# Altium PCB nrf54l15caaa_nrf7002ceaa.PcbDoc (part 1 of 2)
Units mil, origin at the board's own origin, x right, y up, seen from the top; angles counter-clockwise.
Board outline 890.45 x 692.95 mil, 6 copper layers (Top Layer, Mid Layer 1, Mid Layer 2, Mid-Layer 3, Mid-Layer 4, Bottom Layer), stack 38.012 mil thick; 75 components, 69 nets, 285 pads, 346 vias.
Unrouted connection lines stored in the file: 4.
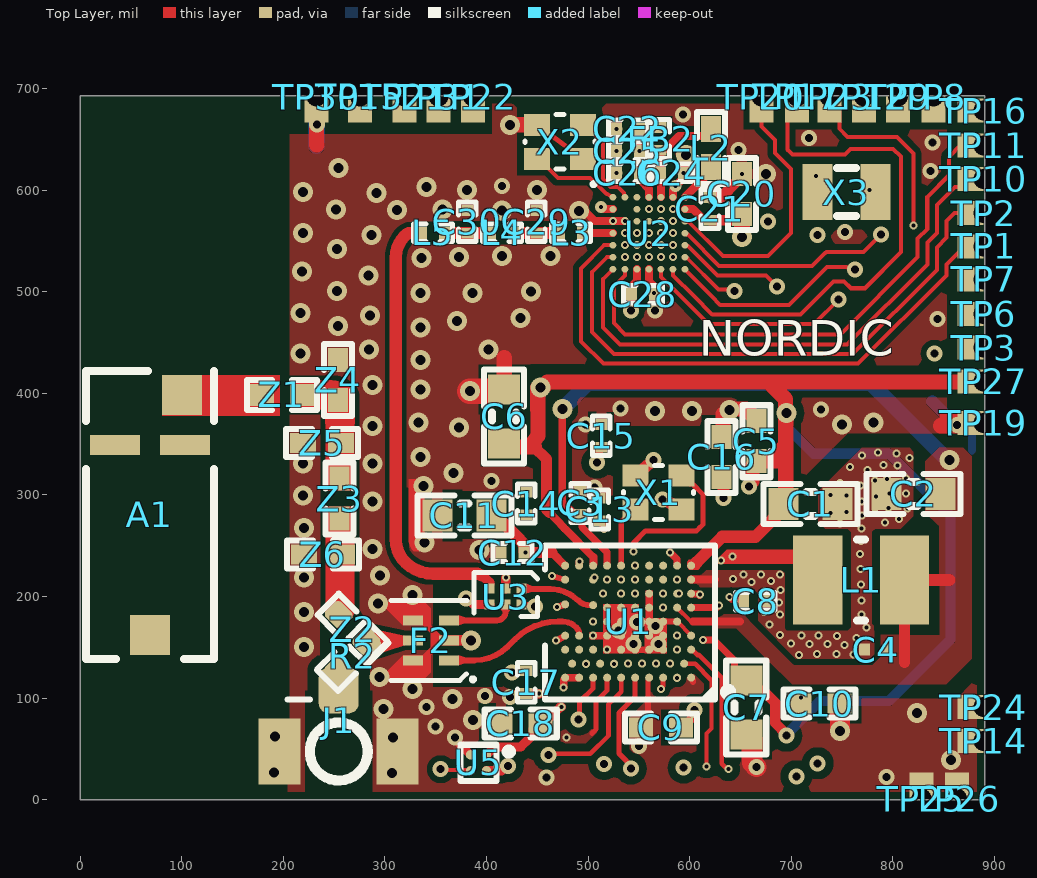
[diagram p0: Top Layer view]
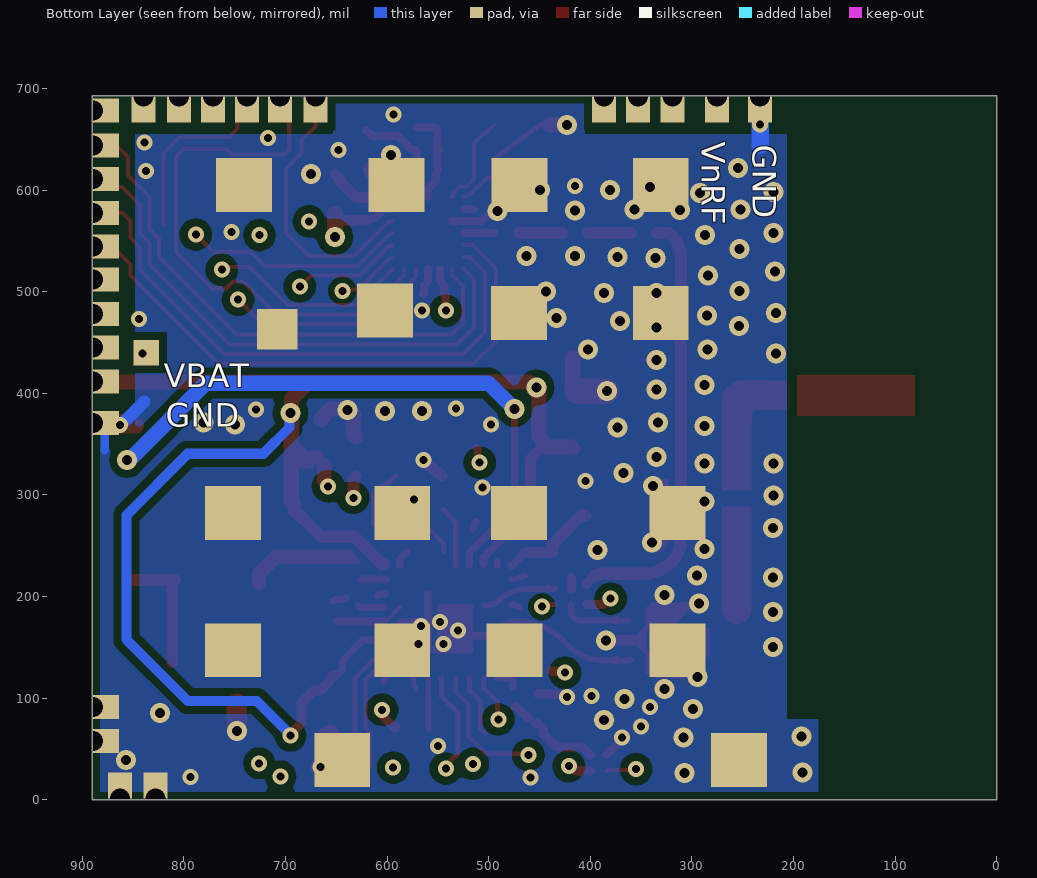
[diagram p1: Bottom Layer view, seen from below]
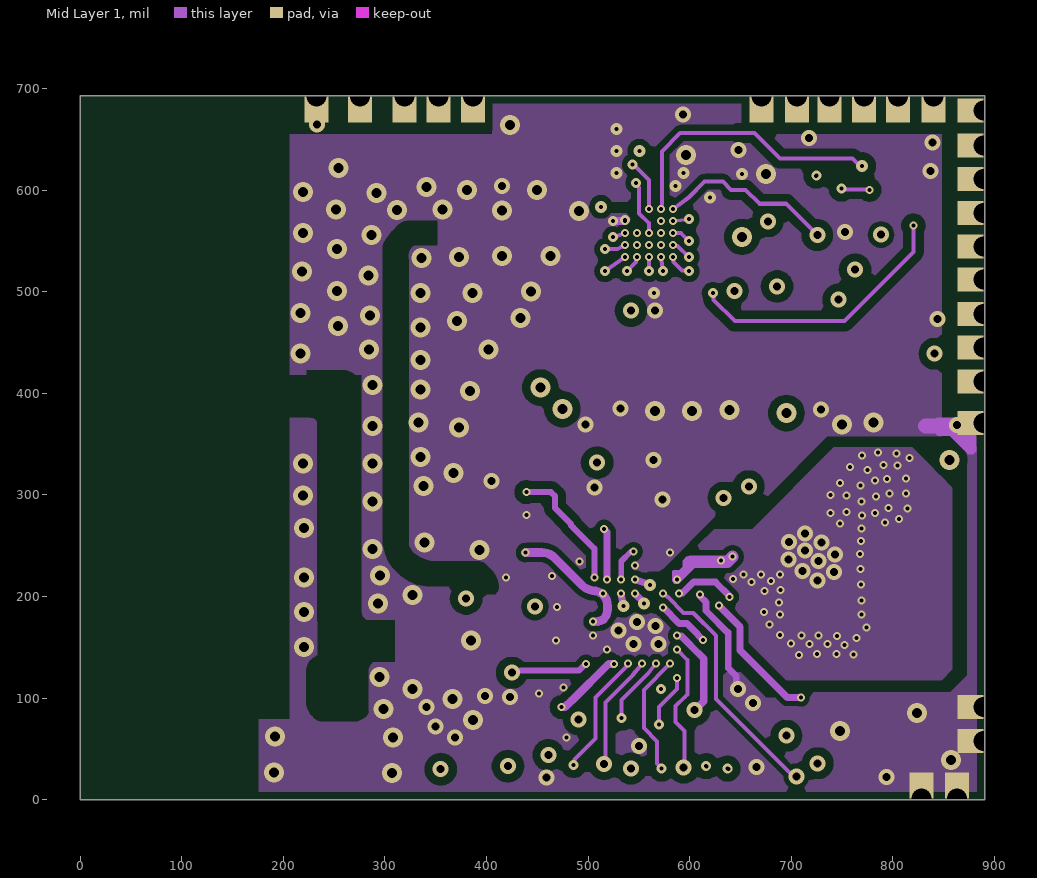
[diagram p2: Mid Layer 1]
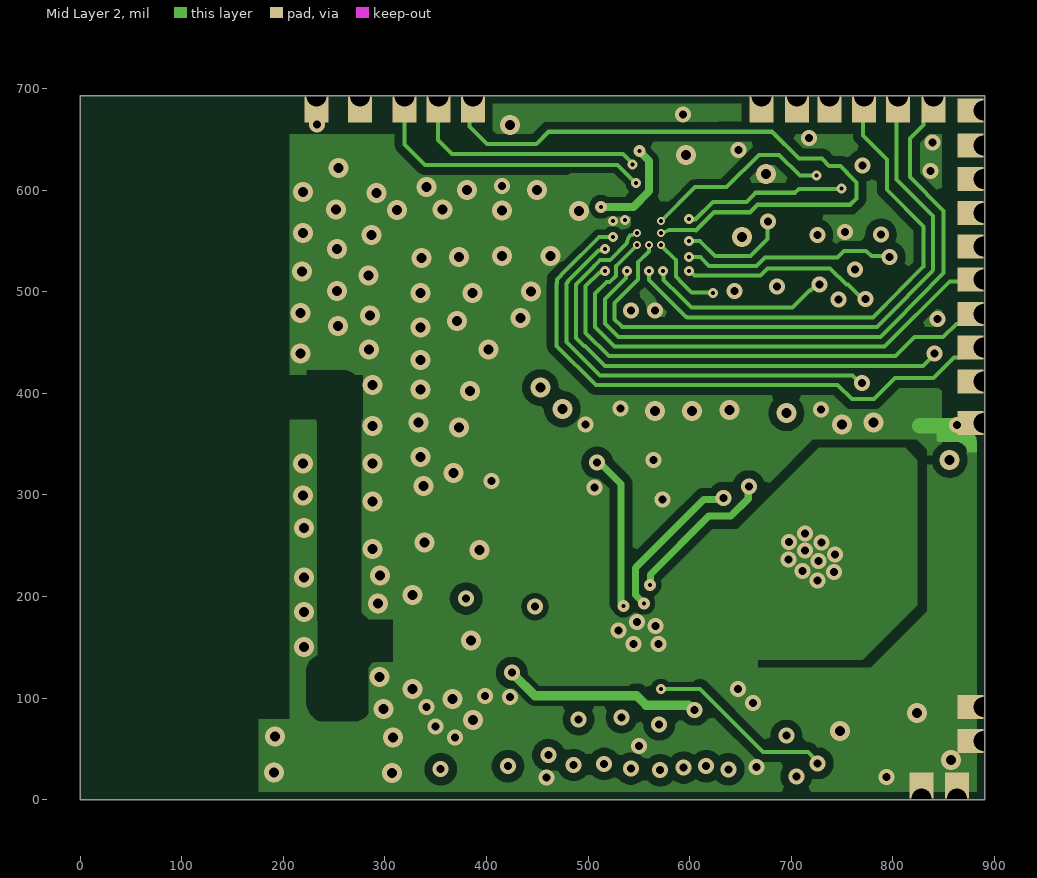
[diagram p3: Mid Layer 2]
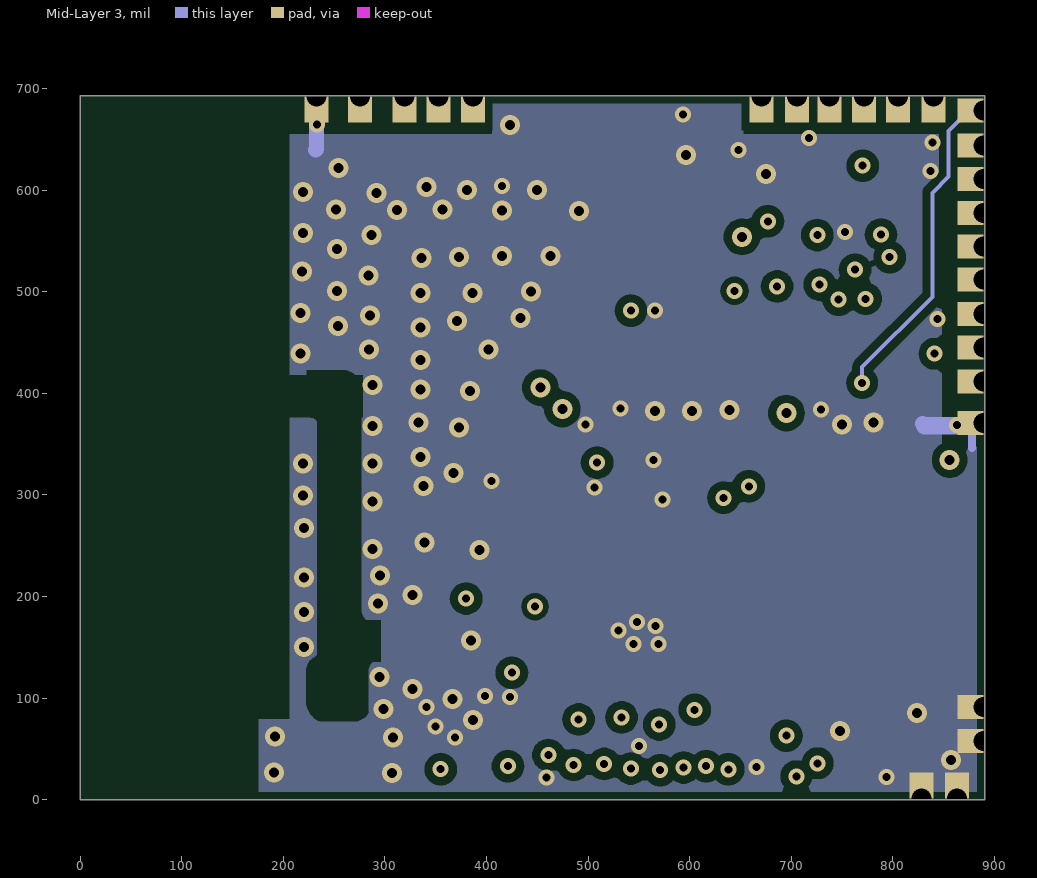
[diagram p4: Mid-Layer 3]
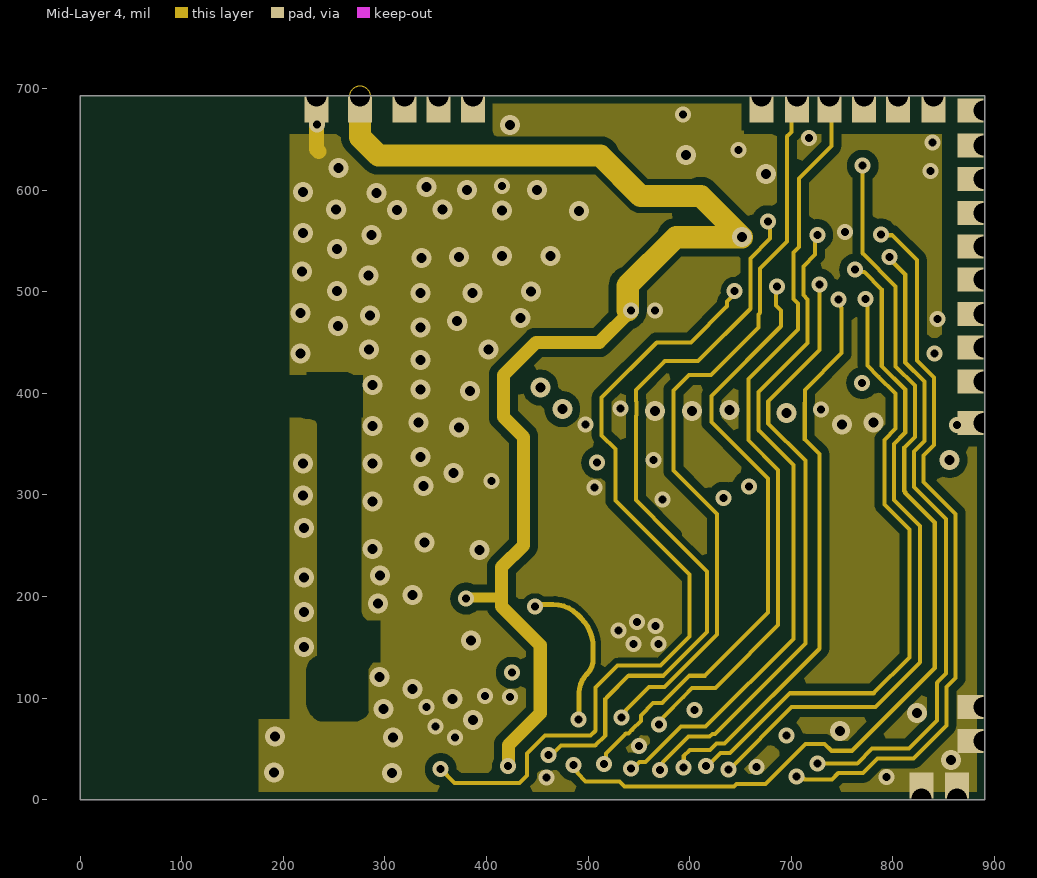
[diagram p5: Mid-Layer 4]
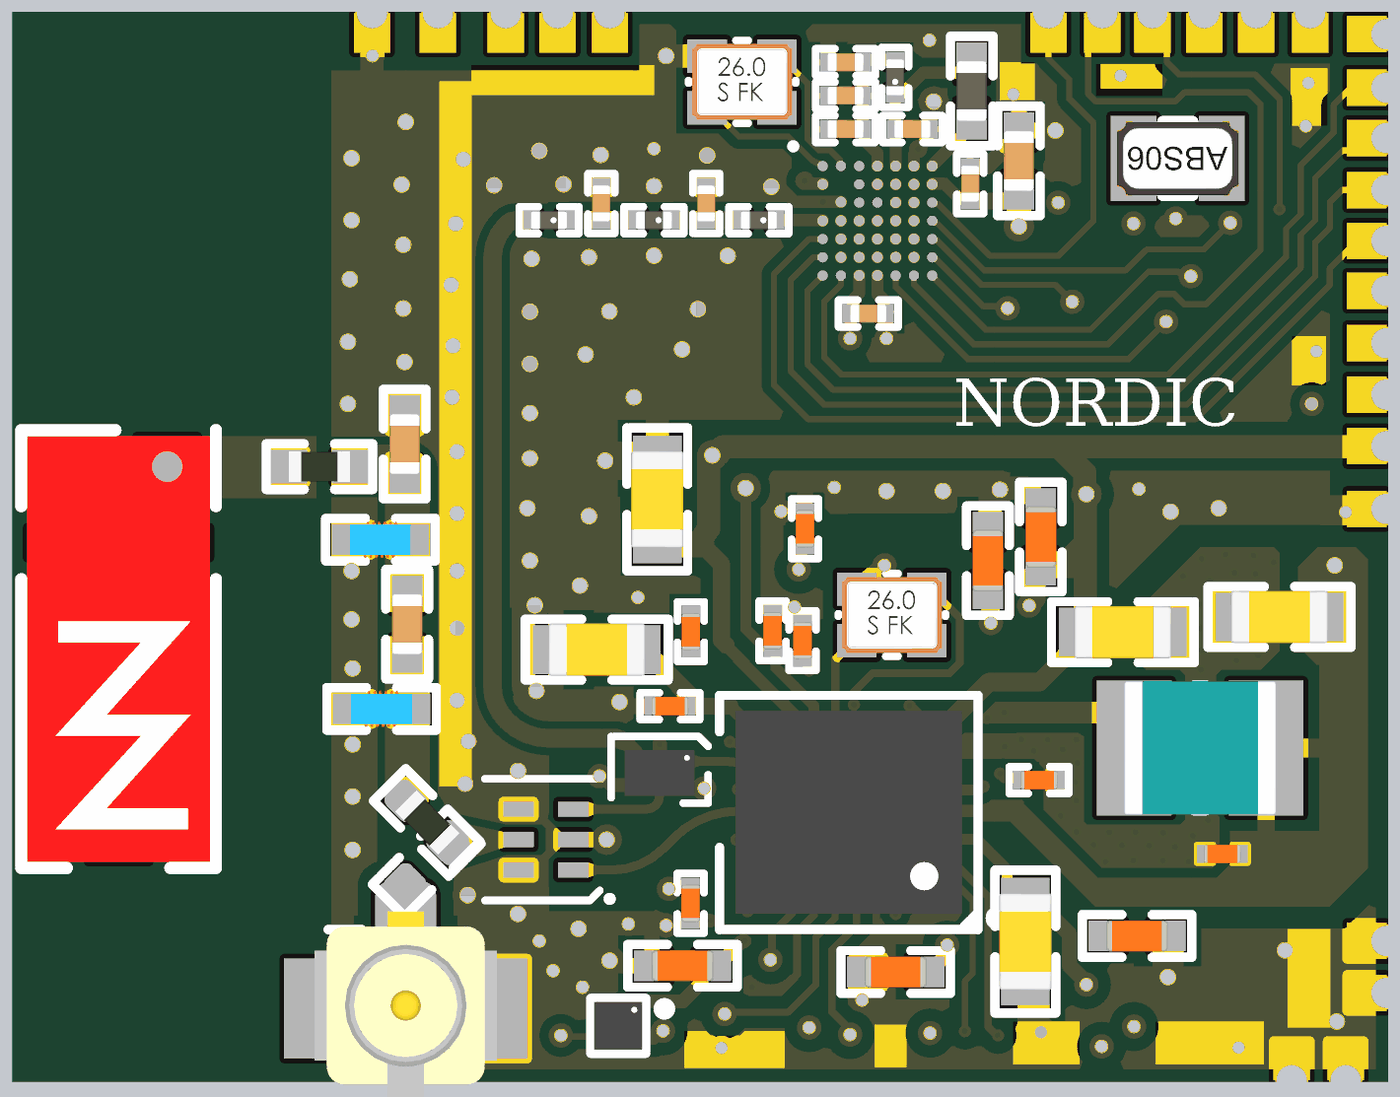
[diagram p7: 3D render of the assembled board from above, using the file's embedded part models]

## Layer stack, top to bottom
Top Solder: solder mask 1.063, Solder Resist, Dk 3.5
Top Layer: signal copper 0.689
Dielectric1: prepreg 3.5, FR-4, Dk 4.2
Mid Layer 1: signal copper 1.417
Dielectric 2: prepreg 3.5, FR-4, Dk 4.2
Mid Layer 2: signal copper 1.417
Dielectric 3: core 17, FR-4, Dk 4.2
Mid-Layer 3: signal copper 1.4
Dielectric 4: dielectric 3.5, FR-4, Dk 4.8
Mid-Layer 4: signal copper 1.4
Dielectric 5: dielectric 3.5, FR-4, Dk 4.8
Bottom Layer: signal copper 0.689
Bottom Solder: solder mask 1.063, Solder Resist, Dk 3.5

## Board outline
0,0 0,692.95 890.45,692.95 890.45,0

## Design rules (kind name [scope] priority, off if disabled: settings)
BoardOutlineClearance BoardOutlineClearance_castholes [HasPad('Free-777') or HasFootprint('Castellated_Hole_0.5mm') or InComponent('J1')] p1: gap=0 ignorepadtopadclearanceinfootprint=FALSE
BoardOutlineClearance [All] p2: gap=7.87 ignorepadtopadclearanceinfootprint=FALSE except(0: Arc-SplitContinuation Track-OutlineEdge Track-SplitContinuation SMDPad-SplitContinuation THPad-SplitContinuation Via-SplitContinuation Fill-SplitContinuation Poly-SplitContinuation Region-SplitContinuation Text-SplitContinuation)
Clearance Clearance_1 [InNet('RF_COM') vs InNet('GND')] p1: gap=4.76 ignorepadtopadclearanceinfootprint=TRUE except(5: Arc-Arc Arc-Track Arc-Fill Arc-Poly Arc-Region Track-Track Track-Fill Track-Poly Track-Region SMDPad-Fill SMDPad-Poly SMDPad-Region Fill-Fill Fill-Poly Fill-Region Poly-Poly Poly-Region Region-Region)
Clearance Clearance_3 [InNetClass('RF') vs InNet('GND')] p2: gap=4.76 ignorepadtopadclearanceinfootprint=TRUE except(5: Arc-Arc Arc-Track Arc-Fill Arc-Poly Arc-Region Track-Track Track-Fill Track-Poly Track-Region SMDPad-Fill SMDPad-Poly SMDPad-Region Fill-Fill Fill-Poly Fill-Region Poly-Poly Poly-Region Region-Region)
Clearance clearance_5 [InNet('P1.06/AIN2_BUCKEN') or InNet('DIGVDD') vs OnLayer('Mid Layer 1')] p3: gap=5 ignorepadtopadclearanceinfootprint=FALSE
Clearance Clearance_2 [InNet('VDD_BUCK') vs OnLayer('Top Layer')] p4: gap=6 ignorepadtopadclearanceinfootprint=FALSE except(3.7: Arc-SMDPad Track-SMDPad; 5: Arc-Arc Arc-Track Track-Track; 5.5: SMDPad-SMDPad; 5.7: THPad-Via)
Clearance Clearance_4 [InNet('NetL3_1')] p5: gap=6 ignorepadtopadclearanceinfootprint=TRUE except(3.94: Arc-Arc Arc-Track Arc-SMDPad Arc-Via Arc-Hole Track-Track Track-SMDPad Track-Via Track-Hole SMDPad-SMDPad SMDPad-THPad SMDPad-Via SMDPad-Hole THPad-Hole Via-Via Via-Hole Fill-Hole Poly-Hole Region-Hole Text-Hole; 5.7: THPad-Via)
Clearance Clearance_bga [WithinRoom('nrf70bga')] p6: gap=5.5 ignorepadtopadclearanceinfootprint=FALSE except(4: Arc-Arc Arc-Track Arc-SMDPad Arc-THPad Arc-Via Track-Track Track-SMDPad Track-THPad Track-Via SMDPad-SMDPad SMDPad-THPad SMDPad-Via THPad-THPad THPad-Via Via-Via; 4.3: Arc-Text Track-Text SMDPad-Text THPad-Text Via-Text Fill-Text Poly-Text Region-Text Text-Text; 5: Arc-Hole Track-Hole SMDPad-Hole THPad-Hole Via-Hole Fill-Hole Poly-Hole Region-Hole Text-Hole)
Clearance Clearance_Top [WithinRoom('BGARoom_1')] p7: gap=3.94 ignorepadtopadclearanceinfootprint=FALSE except(5.91: Arc-Fill Arc-Poly Arc-Region Track-Fill Track-Poly Track-Region SMDPad-Fill SMDPad-Poly SMDPad-Region THPad-Fill THPad-Poly THPad-Region Via-Fill Via-Poly Via-Region Fill-Fill Fill-Poly Fill-Region Poly-Poly Poly-Region Region-Region)
Clearance Clearance_microvia [AsMM(ViaDiameter) = 0.3 vs AsMM(ViaDiameter) = 0.3] p8: gap=3.94 ignorepadtopadclearanceinfootprint=FALSE
Clearance Clearance_U3 [WithinRoom('switch')] p9: gap=5 ignorepadtopadclearanceinfootprint=TRUE
Clearance "Polygon clearance" [(InNamedPolygon('Top_Layer-GND')) or (InNamedPolygon('Mid_Layer_1-GND')) or (InNamedPolygon('Mid_Layer_2-GND')) or (InNamedPolygon('Mid_Layer_3-GND')) or (InNamedPolygon('Mid_Layer_4-GND') or InNamedPolygon('Bottom_Layer-GND'))] p10: gap=8 ignorepadtopadclearanceinfootprint=FALSE
Clearance [All] p11: gap=6 ignorepadtopadclearanceinfootprint=TRUE except(5.5: Arc-Arc Arc-Track Track-Track SMDPad-Region; 5.7: THPad-Via; 5.99: Track-SMDPad Track-Via)
ComponentClearance [All] p1 off: gap=10 collisioncheckmode=3 verticalgap=10 showdistances=FALSE
FabricationTestPointUsage TestPointUsage [All] p1: valid=0 allowmultiple=FALSE
FabricationTestpoint Testpoint [All] p1: side=3 testpointundercomponent=TRUE minsize=40 maxsize=100 preferedsize=60 minholesize=0 maxholesize=40 preferedholesize=32 testpointgrid=1 allowsidetop=TRUE allowsidebottom=TRUE usegrid=TRUE gridtolerance=0.01
Height [All] p1 off: minheight=0 maxheight=1000 prefheight=500
HoleSize [All] p1: absolutevalues=TRUE maxlimit=160 minlimit=3.94 maxpercent=80.000 minpercent=20.000
HoleToHoleClearance HoleToHoleClearance_L1L4 [IsThruVia vs IsThruVia] p1: gap=10 allowstackedmicrovias=TRUE
MinimumAnnularRing [All] p1 off: minimumring=4.92
MinimumSolderMaskSliver [All] p1: minsoldermaskwidth=3.15
PlaneConnect [All] p1: planeconnectstyle=Relief reliefexpansion=20 reliefentries=4 reliefconductorwidth=10 reliefairgap=7.87
PolygonConnect PolygonConnect_1 [isVia and innet(gnd)] p1: connectstyle=Direct reliefconductorwidth=10 reliefentries=4 polygonreliefangle="90 Angle" airgapwidth=10
PolygonConnect [All] p2: connectstyle=Relief reliefconductorwidth=10 reliefentries=4 polygonreliefangle="90 Angle" airgapwidth=7.09
RoomDefinition BGARoom_1 [False vs False] p1: confinementstyle=ConfineIn formatcopy=TRUE lockcomponents=FALSE outline 647.79,495.59 477.52,495.59 477.52,661.61 647.79,661.61
RoomDefinition nrf70bga [False vs False] p2: confinementstyle=ConfineIn formatcopy=TRUE lockcomponents=FALSE outline 426.44,266.89 649.2,266.89 649.2,101.33 426.44,101.33
RoutingVias [All] p1: holewidth=12 width=24 viastyle="Through Hole" minholewidth=3.94 minwidth=7.87 maxholewidth=12 maxwidth=24 useviatemplates=TRUE viatemplateguid#1={2022BCB7-A375-493B-A171-25EA39542BE3} viatemplateguid#2={3ECE8491-CDFF-40CF-8EB3-8F5A41E6EE8D} viatemplateguid#3={55F5E1F8-E6F8-44D2-8975-74334412D251} viatemplateguid#4={ADDB8C30-7D6B-4599-A648-594B4AC96113} viatemplateguid#5={8CFDB15B-AA50-4BCC-A086-0F644C1F84AE} viatemplateguid#6={FFF1F78B-726E-4E76-B445-4EC1AEAF6930} viatemplateguid#7={4B34127C-EC14-4032-8CB6-B1867BF7C970} viatemplateguid#8={8AE5F7F3-E63D-4F88-A284-11A04F05040F} viatemplateguid#9={38DAC5EC-DC23-424B-8D4A-9EDB8A029E0F} viatemplateguid#10={1D06B0E3-B148-46A3-95D7-F0473549D60C} viatemplateguid#11={4724B538-8D9B-404B-8ABB-91D977496468} viatemplatename#1=v20h10m0 viatemplatename#2=v20h10m0_2670034071 viatemplatename#3=v25h10m45 viatemplatename#4=v30h10 viatemplatename#5=v30h10m0_2670034071 viatemplatename#6=v30h10m50 viatemplatename#7=v40h20 viatemplatename#8=v40h20m0mx0_2670034071(1) viatemplatename#9=v40h20_2670034071 viatemplatename#10=v50h25 viatemplatename#11=v50h25_2670034071
SilkToSolderMaskClearance SilkscreenOverComponentPads [IsPad] p1: minsilkscreentomaskgap=10 clearancetoexposedcopper=TRUE
SolderMaskExpansion SolderMaskExpansion_1 [IsVia] p1: expansion=4 istentingtop=TRUE
SolderMaskExpansion [All] p2: expansion=3 istentingtop=FALSE
SupplyNets "Schematic Supply Nets_6" [InNet('GND')] p1: voltage=0.000
SupplyNets "Schematic Supply Nets_5" [InNet('PWRIOVDD')] p2: voltage=0.000
SupplyNets "Schematic Supply Nets_4" [InNet('VDDIO')] p3: voltage=0.000
SupplyNets "Schematic Supply Nets_3" [InNet('VBAT')] p4: voltage=0.000
SupplyNets "Schematic Supply Nets_2" [InNet('VDD_BUCK')] p5: voltage=0.000
SupplyNets "Schematic Supply Nets_1" [InNet('PALDO')] p6: voltage=0.000
SupplyNets "Schematic Supply Nets" [InNet('VDD_nRF')] p7: voltage=0.000
Width Width_U1 [WithinRoom('BGARoom1') or WithinRoom('BGARoom_1')] p1: maxlimit=100 minlimit=3.94 preferedwidth=6 toplayer_maxwidth=78.74 midlayer1_maxwidth=78.74 midlayer2_maxwidth=78.74 bottomlayer_maxwidth=78.74 minimp=50.000000 maximp=50.000000 favimp=50.000000
Width [All] p2: maxlimit=100 minlimit=3.94 preferedwidth=3.94 toplayer_maxwidth=78.74 midlayer1_maxwidth=78.74 midlayer2_maxwidth=78.74 bottomlayer_maxwidth=78.74 minimp=50.000000 maximp=50.000000 favimp=50.000000
21 further rules are at their usual default settings.

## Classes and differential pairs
net class RF: NetF2_3 NetF2_6 NetJ1_1 NetZ1_1 NetZ2_1 RF

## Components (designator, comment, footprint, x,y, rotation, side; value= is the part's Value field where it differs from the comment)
A1 "NN03-320" NN03-320 68.73,280.24 r90 top
C1 "4.7µF" CAPC1608X06L 718.81,291.22 r180 top
C2 "4.7µF" CAPC1608X06L 820.18,301.05 r0 top
C3 "0.22µF" CAPC0603X03L_C 492.06,292.1 r270 top
C4 "0.47µF" CAPC0603X03L_C 783.15,147.64 r0 top
C5 "1.0µF" CAPC1005X04L 665.64,352.85 r90 top
C6 "4.7µF" CAPC1608X06L 417.43,377.18 r270 top
C7 "2.2µF" CAPC1608X06L 655.69,90.83 r90 top
C8 "10nF" CAPC0603X03L_C 664.5,195.41 r180 top
C9 "2.2µF" CAPC1005X04L 571.74,71.18 r180 top
C10 "1.0µF" CAPC1005X04L 727.94,94.5 r0 top
C11 "4.7µF" CAPC1608X06L 378.26,279.88 r0 top
C12 "100nF" CAPC0603X03L_C 425.65,243.3 r0 top
C13 "22nF" CAPC0603X03L_C 511.44,285.77 r270 top
C14 "0.47µF" CAPC0603X03L_C 439.16,291.52 r90 top
C15 "2.2µF" CAPC0603X03L_C 513.03,358.15 r270 top
C16 "1.0µF" CAPC1005X04L 631.44,337.48 r270 top
C17 "100nF" CAPC0603X03L_C 438.97,115.65 r90 top
C18 "2.2µF" CAPC1005X04L 433.73,75.18 r0 top
C20 "10µF" CAPC1005X04L 651.46,596.31 r270 top
C21 "100nF" CAPC0603X03L_C 619.97,581.54 r90 top
C22 "2.2µF" CAPC0603X03L_C 539.26,660.28 r0 top
C24 "2.2µF" CAPC0603X03L_C 582.57,616.98 r180 top
C25 "10nF" CAPC0603X03L_C 539.26,638.63 r0 top
C26 "3.9pF" CAPC0603X03L_C 539.26,616.98 r0 top
C28 "100nF" CAPC0603X03L_C 554.02,497.51 r0 top locked
C29 "1.2pF" CAPC0603X03L_C 449.1,568.76 r270 top
C30 "1.2pF" CAPC0603X03L_C 381.18,568.76 r270 top
F2 "LFD_5G_Diplexer" CAF-50P160X80-6N 345.31,156.87 r180 top locked value=LFD182G45DCHD277
FB2 "120R/0.2A" INDC0603X03L_C 571.35,650.44 r90 top
J1 "U.FL-R-SMT-1" "COAXIAL RF U.FL-R-SMT-1" 254.6,47.45 r180 top
L1 "3.3µH" INDC2520X10N 768.8,216.22 r0 top
L2 "4.7µH" INDC1005X04L 620.95,641.58 r90 top
L3 "3.6nH" INDC0603X03L_C 483.16,557.92 r180 top
L4 "4.6nH" INDC0603X03L_C 415.24,557.92 r180 top
L5 "2.0nH" INDC0603X03L_C 347.33,557.92 r180 top
R2 "0R" RESC1005X04L#1 267.82,141.78 r45 top
TP1 "CH" Castellated_Hole_0.5mm#1 889.45,545.84 r270 top
TP2 "CH" Castellated_Hole_0.5mm#2 889.45,577.46 r270 top
TP3 "CH" Castellated_Hole_0.5mm#2 889.45,444.97 r270 top
TP6 "CH" Castellated_Hole_0.5mm#1 889.45,479.6 r270 top
TP7 "CH" Castellated_Hole_0.5mm#2 889.45,512.22 r270 top
TP8 "CH" Castellated_Hole_0.5mm#1 838.7,691.98 r0 top
TP9 "CH" Castellated_Hole_0.5mm#2 805.08,691.98 r0 top
TP10 "CH" Castellated_Hole_0.5mm#2 889.45,611.09 r270 top
TP11 "CH" Castellated_Hole_0.5mm#3 889.45,644.71 r270 top
TP12 "CH" Castellated_Hole_0.5mm#2 771.46,691.98 r0 top
TP14 "CH" Castellated_Hole_0.5mm#2 889.45,57.63 r270 top
TP15 "CH" Castellated_Hole_0.5mm#2 275.46,691.98 r0 top
TP16 "CH" Castellated_Hole_0.5mm#4 889.45,678.33 r90 top
TP17 "CH" Castellated_Hole_0.5mm#1 704.21,691.98 r0 top
TP19 "CH" Castellated_Hole_0.5mm#5 889.45,368 r90 top
TP20 "CH" Castellated_Hole_0.5mm#4 670.6,691.98 r180 top
TP21 "CH" Castellated_Hole_0.5mm#4 319.33,691.98 r180 top
TP22 "CH" Castellated_Hole_0.5mm#4 386.56,691.98 r180 top
TP23 "CH" Castellated_Hole_0.5mm#4 737.83,691.98 r180 top
TP24 "CH" Castellated_Hole_0.5mm#4 889.45,91.24 r90 top
TP25 "CH" Castellated_Hole_0.5mm#4 828.08,0.98 r0 top
TP26 "CH" Castellated_Hole_0.5mm#6 861.7,0.98 r0 top
TP27 "CH" Castellated_Hole_0.5mm#6 889.45,410.34 r90 top
TP30 "CH" Castellated_Hole_0.5mm#4 232.78,691.98 r180 top
TP31 "CH" Castellated_Hole_0.5mm#4 352.95,691.98 r180 top
U1 "nRF7002-CEAA" nRF7002_WLCSP_R2 541.37,176.06 r180 top locked
U2 "nRF54L15-CAAABB0" BGA49C30P7x7_2245X2451X48 556.63,557.55 r0 top locked
U3 "BGS12xN6" TSNP-6-8 418.91,200 r270 top value=BGS12SN6
U5 "TCK106AG" BGA4C40P2X2_76X76X62 392.14,36.31 r270 top
X1 "40MHz" BT-XTAL_1612 569.29,302.32 r0 top
X2 "32MHz" BT-XTAL_1612 472.33,647.49 r0 top
X3 "32.768kHz" XTAL_2012 754.3,597.9 r180 top
Z1 "0R" RESC1005X04L#2 198.73,398.35 r180 top
Z2 "0R" RESC1005X04L#1 268.52,168 r315 top
Z3 "0.5pF" CAPC1005X04L 255.53,296.33 r270 top
Z4 "0.6pF" CAPC1005X04L 253.9,413 r90 top
Z5 "2.6nH" INDC1005X04L_WW 238.23,351.06 r0 top
Z6 "3.5nH" INDC1005X04L_WW 238.93,241.53 r0 top

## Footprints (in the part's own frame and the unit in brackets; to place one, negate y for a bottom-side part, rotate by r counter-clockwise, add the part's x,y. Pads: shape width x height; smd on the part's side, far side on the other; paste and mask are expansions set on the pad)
BGA4C40P2X2_76X76X62 [mm] "BGA, 4-Leads, Body 0.8x0.8mm,  Pitch 0.40mm"
  round 0.235 smd mask+0.04: A1(-0.2,0.2) A2(0.2,0.2) B1(-0.2,-0.2) B2(0.2,-0.2)
  silkscreen extent -0.45,-0.45 0.45,0.81, body extent -0.39,-0.39 0.4,0.4, height 0.55
BGA49C30P7x7_2245X2451X48 [mm] "BGA/CSP, 47-Leads, Body 0.42x2.451mmx2.245mm, Pitch 0.30mm"
  round 0.17 smd mask+0.005: A1(-0.816,0.9) A2(-0.516,0.9) A3(-0.216,0.9) A4(0.084,0.9) A5(0.384,0.9) A6(0.684,0.9) A7(0.984,0.9) B1(-0.816,0.6) B3(-0.216,0.6) B4(0.084,0.6) B5(0.384,0.6) B6(0.684,0.6) B7(0.984,0.6) C2(-0.516,0.309) C3(-0.216,0.3) C4(0.084,0.3) C5(0.384,0.3) C6(0.684,0.3) C7(0.984,0.3) D1(-0.816,0) D2(-0.516,0) D3(-0.216,0) D4(0.084,0) D5(0.384,0) D6(0.684,0) D7(0.984,0) E1(-0.816,-0.3) E2(-0.516,-0.3) E3(-0.216,-0.3) E4(0.084,-0.3) E5(0.384,-0.3) E6(0.684,-0.3) E7(0.984,-0.3) F1(-0.816,-0.6) F2(-0.516,-0.6) F3(-0.216,-0.6) F4(0.084,-0.6) F5(0.384,-0.6) F6(0.684,-0.6) F7(0.984,-0.6) G1(-0.816,-0.9) G2(-0.516,-0.9) G3(-0.216,-0.9) G4(0.084,-0.9) G5(0.384,-0.9) G6(0.684,-0.9) G7(0.984,-0.9)
  silkscreen extent -1.35,1.18 -1.25,1.27, body extent -1.23,-1.12 1.22,1.12, height 0.42
BT-XTAL_1612 [mm] "Crystal 1.6 x 1.2 mm"
  rect 0.65x0.55 smd: 1(-0.575,-0.425) 2(0.575,-0.425) 3(0.575,0.425) 4(-0.575,0.425)
  silkscreen extent -0.88,-0.68 0.88,0.68, body extent -0.83,-0.63 0.83,0.63, height 0.41
CAF-50P160X80-6N [mm] "Chip Array, Flat, 6-Leads, Pitch 0,50mm,  Body 1,60x0,80mm,  IPC Medium Density"
  rect 0.5x0.25 smd mask+0.08: 1(-0.45,0.5) 2(-0.45,0) 3(-0.45,-0.5) 5(0.45,-0.5) 6(0.45,0) 7(0.45,0.5)
  Top Layer region: 0.693,0.375 0.2,0.375 0,0.175 0,-0.175 0.2,-0.375 0.699,-0.375 1.175,-0.852 1.175,-0.95 0.15,-0.95 0,-0.8 0,-0.375 -0.25,-0.125 -0.8,-0.125 -0.9,-0.225 -1,-0.225 -1,0.225 -0.9,0.225 -0.8,0.125 -0.25,0.125 0,0.375 0,0.8 0.15,0.95 1.175,0.95 1.175,0.857
  silkscreen extent -1.1,-1 1,1.02, body extent -0.5,-0.88 0.5,0.88, height 0.67
CAPC0603X03L_C [mm] "Chip Capacitor, 2-Leads, Body 0.6x0.3mm, IPC High Density"
  rect 0.27x0.3 smd mask+0.05: 1(-0.285,0) 2(0.285,0)
  silkscreen extent -0.49,-0.22 0.49,0.22, body extent -0.3,-0.15 0.31,0.15, height 0.3
CAPC1005X04L [mm] "Chip Capacitor, 2-Leads, Body 1.0x0.5mm, IPC High Density"
  rect 0.6x0.5 smd: 1(-0.5,0) 2(0.5,0)
  silkscreen extent -0.9,-0.35 0.9,0.35, body extent -0.51,-0.25 0.51,0.25, height 0.5
CAPC1608X06L [mm] "Chip Capacitor, 2-Leads, Body 1.6x0.8mm, IPC High Density"
  rect 0.75x0.8 smd: 1(-0.675,0) 2(0.675,0)
  silkscreen extent -1.17,-0.5 1.17,0.5, body extent -0.8,-0.43 0.8,0.43, height 0.8
Castellated_Hole_0.5mm#1 [mm]
  rect 0.6x0.65 hole 0.5 copper offset 0,-0.325: 1(0.033,0)
Castellated_Hole_0.5mm#2 [mm]
  rect 0.6x0.65 hole 0.5 copper offset 0,-0.325: 1(0,0)
Castellated_Hole_0.5mm#3 [mm]
  rect 0.6x0.65 hole 0.5 copper offset 0,-0.325: 1(0.025,0)
Castellated_Hole_0.5mm#4 [mm]
  rect 0.6x0.65 hole 0.5 copper offset 0,0.325: 1(0,0)
Castellated_Hole_0.5mm#5 [mm]
  rect 0.6x0.65 hole 0.5 copper offset 0,0.325: 1(0.076,0)
Castellated_Hole_0.5mm#6 [mm]
  rect 0.6x0.65 hole 0.5 copper offset 0,0.325: 1(0.033,0)
"COAXIAL RF U.FL-R-SMT-1" [mm]
  rrect50% 1x1.143 smd: 1(0,-1.525)
  rect 1.05x1.651 smd: 2(-1.475,0) 2(1.475,0)
  Top Layer pour cut-out: 0.85,1.3 -0.85,1.3 -0.85,-1.525 0.85,-1.525
  silkscreen extent -0.72,-1.3 1.28,0.72, body extent -1.5,-1.6 1.5,1.5, height 1.25
INDC0603X03L_C [mm] "Chip Inductor, 2-Leads, Body 0.6x0.3mm, IPC High Density"
  rect 0.27x0.3 smd: 1(-0.285,0) 2(0.285,0)
  silkscreen extent -0.49,-0.22 0.49,0.22, body extent -0.3,-0.15 0.3,0.15, height 0.3
INDC1005X04L [mm] "Chip Inductor, 2-Leads, Body 1.0x0.5mm, IPC High Density"
  rect 0.65x0.5 smd: 1(-0.475,0) 2(0.475,0)
  silkscreen extent -0.9,-0.35 0.9,0.35, body extent -0.5,-0.25 0.5,0.25, height 0.5
INDC1005X04L_WW [mm] "Chip Inductor, 2-Leads, Body 1.0x0.5mm, IPC High Density"
  rect 0.65x0.5 smd: 1(-0.475,0) 2(0.475,0)
  silkscreen extent -0.9,-0.35 0.9,0.35, body extent -0.5,-0.3 0.5,0.3, height 0.51
INDC2520X10N [mm] "Chip Inductor, 2-Leads, Body 2,50x2,00mm, IPC Medium Density"
  rect 1.23x2.22 smd: 1(-1.085,0) 2(1.085,0)
  silkscreen extent -0.1,-1.01 0.1,1.01, body extent -1.25,-1.1 1.25,1.1, height 1.98
NN03-320 [mm]
  rect 1x1 smd: 1(-3,0) 4(3,-0.8)
  rect 0.5x1.25 smd: 2(1.75,-0.875) 3(1.75,0.875)
  Multi-Layer pour cut-out: -3.5,1.5 3.5,1.5 3.5,-1.5 -3.5,-1.5
  silkscreen extent -3.6,-1.6 3.6,1.6, body extent -3.5,-1.5 3.5,1.5, height 2.01
nRF7002_WLCSP_R2 [mm] "BGA, 90-Leads, Body 3.72x3.34mmx0.54mm, Pitch 0.34mm"
  round 0.2 smd mask-0.01: A1(-1.526,1.422) A3(-1.176,1.422) A5(-0.826,1.422) A7(-0.476,1.422) A9(-0.126,1.422) A11(0.224,1.422) A13(0.574,1.422) A16(0.924,1.422) A18(1.274,1.422) A20(1.624,1.422) B2(-1.352,1.072) B4(-1.002,1.072) B6(-0.652,1.072) B8(-0.302,1.072) B10(0.049,1.072) B12(0.399,1.072) B15(0.749,1.072) B17(1.099,1.072) B19(1.449,1.072) C1(-1.526,0.722) C3(-1.176,0.722) C5(-0.826,0.722) C7(-0.476,0.722) C9(-0.126,0.722) C11(0.224,0.722) C13(0.574,0.722) C16(0.924,0.722) C18(1.274,0.722) C20(1.624,0.722) D1(-1.526,0.372) D3(-1.176,0.372) D5(-0.826,0.372) D7(-0.476,0.372) D9(-0.126,0.372) D11(0.224,0.372) D13(0.574,0.372) D16(0.924,0.372) D18(1.274,0.372) D20(1.624,0.372) E3(-1.176,0.022) E5(-0.826,0.022) E7(-0.476,0.022) E9(-0.126,0.022) E11(0.224,0.022) E13(0.574,0.022) E16(0.924,0.022) F1(-1.526,-0.328) F3(-1.176,-0.328) F5(-0.826,-0.328) F7(-0.476,-0.328) F9(-0.126,-0.328) F11(0.224,-0.328) F13(0.574,-0.328) G16(0.924,-0.391) H20(1.624,-0.411) J1(-1.526,-0.679) J3(-1.176,-0.679) J5(-0.826,-0.679) J7(-0.476,-0.679) J9(-0.126,-0.679) J11(0.224,-0.679) J14(0.677,-0.679) K1(-1.526,-1.029) K3(-1.176,-1.029) K5(-0.826,-1.029) K7(-0.476,-1.029) K9(-0.126,-1.029) K11(0.224,-1.029) K13(0.574,-1.029) K16(0.924,-1.029) K20(1.624,-1.029) L1(-1.526,-1.379) L3(-1.176,-1.379) L5(-0.826,-1.379) L7(-0.476,-1.379) L9(-0.126,-1.379) L11(0.224,-1.379) L13(0.574,-1.379) L16(0.924,-1.379) L18(1.274,-1.379) L20(1.624,-1.379)
  silkscreen extent -2.53,-1.89 2.13,1.97, body extent -1.86,-1.63 1.86,1.71, height 0.54
RESC1005X04L#1 [mm] "Chip Resistor, 2-Leads, Body 1.0x0.5mm, IPC High Density"
  rrect50% 0.6x0.55 smd mask+0.05: 1(-0.5,0) 2(0.5,0)
  silkscreen extent -0.88,-0.38 0.88,0.38
RESC1005X04L#2 [mm] "Chip Resistor, 2-Leads, Body 1.0x0.5mm, IPC High Density"
  rect 0.6x0.55 smd mask+0.05: 1(-0.5,0) 2(0.5,0)
  silkscreen extent -0.87,-0.38 0.88,0.38, body extent -0.5,-0.25 0.5,0.25, height 0.3
TSNP-6-8 [mm] "LGA, 6-Leads, Body 0,70x1,10mmx0,38mm, Pitch 0,40mm"
  rect 0.25x0.25 smd paste-0.03 mask+0.038: 1(-0.2,0.4) 2(-0.2,0) 3(-0.2,-0.4) 4(0.2,-0.4) 5(0.2,0) 6(0.2,0.4)
  silkscreen extent -0.6,-0.8 0.41,0.8, body extent -0.38,-0.58 0.38,0.58, height 0.38
XTAL_2012 [mm] "XTAL SMD 2.0 x 1.2 mm"
  rect 0.75x1.4 smd: 1(-0.725,0) 2(0.725,0)
  silkscreen extent -0.24,-0.6 0.24,0.6, body extent -1,-0.61 1,0.61, height 0.6

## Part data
A1: "Dual-Band GNSS and Wi-Fi/BluetoothAntenna", Manufacturer=Ignion
C1 C2 C6 C11: library part C0603-4µ7-25V-X6S-GRM188C81E475KE11, "Capacitor, Ceramic, 4.7µF 25V X6S 0603,±10%", Manufacturer=Murata, Manufacturer Part Number=GRM188C81E475KE11D
C3: library part C0201-220n-10V-X5R-GRM033R61A224KE90, "Capacitor, Ceramic, 0.22µF 10V X5R 0201, ±10%", Manufacturer=Murata, Manufacturer Part Number=GRM033R61A224KE90D
C4 C14: library part C0201-470n-6.3V-X5R-GRM033R60J474KE90, "Capacitor, Ceramic, 0.47µF 6.3V X5R 0201,±10%", Manufacturer=Murata, Manufacturer Part Number=GRM033R60J474KE90D
C5: library part C0402-1µ0-35V-X5R-GRM155R6YA105KE11, "Capacitor, Ceramic, 1.0µF 35V X5R 0402,±10%", Manufacturer=Murata, Manufacturer Part Number=GRM155R6YA105KE11D
C7: library part C0603-2µ2-16V-X7S-GRM188C71C225KE11, "Capacitor, Ceramic, 2.2µF 16V X7S 0603,±10%", Manufacturer=Murata, Manufacturer Part Number=GRM188C71C225KE11D
C8: library part C0201-10n-16V-X7R-GRM033R71C103KE14, "Capacitor, Ceramic, 10nF 16V X7R 0201,±10%", Manufacturer=Murata, Manufacturer Part Number=GRM033R71C103KE14D
C9: library part C0402-2µ2-25V-X5R-GRM155R61E225KE11, "Capacitor, Ceramic, 2.2µF 25V X5R 0402,±10%", Manufacturer=Murata, Manufacturer Part Number=GRM155R61E225KE11D
C10: library part C0402-1µ0-16V-X6S-GRM155C81C105KE11J, "Capacitor, Ceramic, 1.0µF 16V X6S 0402,±10%", Manufacturer=Murata, Manufacturer Part Number=GRM155C81C105KE11J
C12 C17: library part C0201-100n-16V-X7S-GRM033C71C104KE14, "Capacitor, Ceramic, 100nF 16V X7S 0201,±10%", Manufacturer=Murata, Manufacturer Part Number=GRM033C71C104KE14D
C13: library part C0201-22n-10V-X5R-GRM033R61A223KE84, "Capacitor, Ceramic, 22nF 10V X5R 0201,±10%", Manufacturer=Murata, Manufacturer Part Number=GRM033R61A223KE84D
C15: library part C0201-2µ2-10V-X5R-GRM033R61A225KE47, "Capacitor, Ceramic, 2.2µF 10V X5R 0201,±10%", Manufacturer=Murata, Manufacturer Part Number=GRM033R61A225KE47D
C16: library part C0402-1µ0-10V-X7S-GRM155C71A105KE11, "Capacitor, Ceramic, 1.0µF 10V X7S 0402,±10%", Manufacturer=Murata, Manufacturer Part Number=GRM155C71A105KE11D
C18: library part C0402-2µ2-16V-X6S-M, "CAP MLCC 2.2UF 16V X6S 0402", Manufacturer="Taiyo Yuden", Manufacturer Part Number=EMK105CC6225KV-F
C20: library part C0402-10µF-6.3V-X6S, "Capacitor, X6S, ±20%, 6.3V", Manufacturer=N.A.
C21 C28: library part C0201-100n-10V-X7R, "Capacitor, X7R, ±10%", Manufacturer=N.A.
C22 C24: library part C0201-2µ2-2.5V-X6T-GRM033D80E225ME47D, "Capacitor, Ceramic, 2.2µF 2.5V X6T 0201,±20%", Manufacturer=Murata, Manufacturer Part Number=GRM033D80E225ME47D
C25: library part C0201-10n-6.3V-X7R, "Capacitor, X7R, 6.3V", Manufacturer=Murata, Manufacturer Part Number=GRM033R70J103KA01D
C26: library part C0201-3.9p-HQ-Murata, "Capacitor, NP0, ±0.05pF, 25V", Manufacturer=Murata, Manufacturer Part Number=GJM0333C1E3R9WB01
C29 C30: library part C0201-1.2p-HQ-Murata, "Capacitor, NP0, ±0.05pF, 50V", Manufacturer=Murata, Manufacturer Part Number=GJM0335C1H1R2WB01D
F2: library part LFD182G45DCHD277, "Signal Conditioning 2.4GHz and 5GHz Diplexer", Manufacturer=Murata
FB2: library part FB0201-120R@100M-200mA-BLM03AG121SN1D, "Ferrite Bead, 120 Ohm @ 100MHz, 200mA, 500 mOhm Max", Manufacturer=Murata, Manufacturer Part Number=BLM03AG121SN1D
J1: "Ultra Small Surface Mount Coaxial Connectors, 50 Ohm, SMD", Manufacturer=Hirose
L1: library part L1008-3µ3-LQM2HPN3R3MGCL, "Inductor, 1A, ±20%, 200mOhm", Manufacturer=Murata, Manufacturer Part Number=LQM2HPN3R3MGCL
L2: library part L0402-4µ7-PLEA67BCA4R7M-1PT00, "Inductor, 300mA, ±20%, 1.08R", Manufacturer="TDK Corporation", Manufacturer Part Number=PLEA67BCA4R7M-1PT00
L3: library part L0201-3n6-HQ-Murata, "Inductor, 500mA, ±0.1ｎH, 170mOhm", Manufacturer=Murata, Manufacturer Part Number=LQP03HQ3N6B02
L4: library part L0201-4n6-HQ-Murata, "Inductor, 400mA, ±3%, 250mOhm", Manufacturer=Murata, Manufacturer Part Number=LQP03HQ4N6H02
L5: library part L0201-2n0-HQ-Murata, "Inductor, 600mA, ±0.1ｎH, 120mOhm", Manufacturer=Murata, Manufacturer Part Number=LQP03HQ2N0B02
R2 Z1 Z2: library part R0402-0R, "Resistor, ±5%, 0.063W", Manufacturer=N.A.
TP1 TP2 TP3 TP6 TP7 TP8 TP9 TP10 TP11 TP12 TP14 TP15 TP16 TP17 TP19 TP20 TP21 TP22 TP23 TP24 TP25 TP26 TP27 TP30 TP31: library part "Castellated Hole 0.5mm", "Castellated Hole 0.5mm", Manufacturer=N.A.
U1: "Wi-fi Dual Band Companion chip WLCSP", Manufacturer="Nordic Semiconductor"
U2: "Multi-protocol Bluetooth Low Energy, IEEE 802.15.4, ANT and 2.4GHz proprietary system-on-chip", Manufacturer="Nordic Semiconductor"
U3: library part BGS12SN6, "Wideband SPDT RF Switch, 50MHz-6GHz. Max 30dBm, 1.8-3.5V", Manufacturer="Infineon Technologies", Manufacturer Part Number=BGS12SN6E6327XTSA1
U5: "1.0 A Load Switch IC with Slew Rate Control Driver in Ultra Small Package", Manufacturer=Toshiba, Manufacturer Part Number=TCK106AG,LF
X1: library part XTAL_SMD1612_40MHz_8p_40_85, "XTAL SMD 1612, 40MHz, Cl=8pF, Total Tol: ±10ppm, -40-85C", Manufacturer="Abracon Corporation", Manufacturer Part Number=ABM12W-40.0000MHZ-8-D1X-T3
X2: library part XTAL_SMD1612_32MHz_8pF_Kyocera, "XTAL SMD 1612, 32MHz, Cl=8pF, Tot: ±40ppm, Aging: ±1ppm/year", Manufacturer=Kyocera, Manufacturer Part Number=CX1612DB32000D0WZRC3
X3: library part XTAL_SMD2012_32.768kHz_9pF_TXC, "XTAL SMD 2012, 32.768kHz, 9pF, ±20ppm", Manufacturer="TXC Corporation", Manufacturer Part Number=9HT11-32.768KDZC-T
Z3: library part C0402-0.5p-HQ-Murata, "Capacitor, NP0, ±0.05pF, 50V", Manufacturer=Murata, Manufacturer Part Number=GJM1555C1HR50WB01
Z4: library part C0402-0.6p, "Chip Cap 0402", Manufacturer=N.A.
Z5: library part L0402-2n6-Wirewound-Murata, "Inductor, 850mA, ±0.1nH, 50mΩ", Manufacturer=Murata, Manufacturer Part Number=LQW15AN2N6B00
Z6: library part L0402-3n5-Wirewound-Murata, "Inductor, 900mA, ±0.2nH, 40mΩ", Manufacturer=Murata, Manufacturer Part Number=LQW15AN3N5C10

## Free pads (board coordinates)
  rect 40x40 smd far side mask+2: 2(708,463)
  rect 55x53 smd far side mask+2: 3(253.71,39.08) 3(314.18,282.18) 3(314.18,147.18) 3(330.73,479.18) 3(330.73,605.18) 3(469.73,605.18) 3(470.18,282.18) 3(470.18,479.18) 3(474.64,147.18) 3(585.18,147.18) 3(585.18,282.18) 3(590.73,605.18) 3(602,481.36) 3(644.16,39.08) 3(740.73,605.18) 3(751.71,147.18) 3(751.71,282.18)
  rect 25x25 smd far side: 4(837.16,440)

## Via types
v1: diameter 7.87, hole 3.94, Top Layer to Mid Layer 1, tented top, 93 vias
v2: diameter 19.68, hole 9.84, Top Layer to Bottom Layer, tented both sides, 83 vias
v3: diameter 15.75, hole 7.87, Top Layer to Bottom Layer, tented both sides, 58 vias
v4: diameter 7.87, hole 3.94, Top Layer to Mid Layer 1, tented both sides, 43 vias
v5: diameter 9.84, hole 3.94, Mid Layer 1 to Mid Layer 2, tented top, 22 vias
v6: diameter 15.75, hole 7.87, Mid Layer 1 to Mid Layer 2, tented both sides, 12 vias
v7: diameter 15.75, hole 7.87, Mid Layer 2 to Mid-Layer 4, tented both sides, 11 vias
v8: diameter 11.81, hole 3.94, Top Layer to Mid Layer 1, tented top, 9 vias
v9: diameter 7.87, hole 3.94, Mid Layer 1 to Mid Layer 2, tented top, 6 vias
v10: diameter 11.81, hole 3.94, Mid Layer 1 to Mid Layer 2, 3 vias
v11: diameter 11.81, hole 3.94, Mid Layer 1 to Mid Layer 2, tented both sides, 3 vias
v12: diameter 9.84, hole 3.94, Mid Layer 1 to Mid Layer 2, 2 vias
v13: diameter 11.81, hole 3.94, Top Layer to Mid Layer 1, tented both sides, 1 vias

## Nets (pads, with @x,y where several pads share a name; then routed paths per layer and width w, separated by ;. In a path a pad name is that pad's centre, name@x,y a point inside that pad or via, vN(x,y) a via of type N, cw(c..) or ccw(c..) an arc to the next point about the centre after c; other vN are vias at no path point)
AFELDO: C16.2 U1.J9 | length 185.2
  Top Layer w12: C16.2@631.44,317.8 633.18,316.06 633.18,297.28 v3(633.32,297.14)
  Mid Layer 1 w7: v4(546.34,202.78) v11@554.91,194.2
  Mid Layer 2 w7: v11(554.91,193.3) 546.57,201.64 546.57,228.23 585.99,267.65 614,295.66 629.84,295.66 v3@631.32,297.14
BUCKOUT: L1.1 U1.K3 | length 143.5
  Top Layer w14: v4(642.08,239.18) 709.37,239.18 726.09,222.47 L1.1@726.09,213.22
  Mid Layer 1 w12: 600.76,234.28 637.18,234.28 v4(642.08,239.18)
  other v4: 587.74,216.56 631.07,235.6
BUCKVMID: C8.2 U1.J3 | length 74
  Top Layer w7: v1@640.11,199.01 642.25,196.87 649.72,196.87 651.82,196.87 C8.2@653.09,195.6
  Mid Layer 1 w6.5: v4@589.86,203.06 589.95,203.06 590.38,203.49 593.01,203.49 603.82,214.3 625.74,214.3 ; 625.74,213.74 638.63,200.85 639.08,200.42 v1@639.32,200.42
  other v1: 639.32,199.6
  other v4: 589.32,202.8
DCC: L2.1 U2.A7 | length 39.7
  Top Layer w7.87: U2.A7@595.36,593.36 619.97,617.96 L2.1@619.97,622.88
DECA: C22.2 C25.2 C26.2 FB2.2 U2.A4 U2.B1 | length 200.7
  Top Layer w7.87: v8@515.18,581.54 U2.B1@524.49,581.54 ; C25.2@549.1,640.01 v8(550.48,638.63) ; U2.A4@559.93,593.36 559.93,601.23 551.86,609.3 551.86,617.57 550.48,618.95 v8(550.48,638.63) ; FB2.2@571.34,661.67 551.86,661.67 C22.2@550.48,660.28 v8(550.48,638.63)
  Mid Layer 2 w7.87: v10(512.68,583.51) 544.63,583.51 560.18,599.06 560.18,628.59 v10(550.48,638.25)
  other v8: 512.68,583.51
DECD: C24.2 FB2.1 L2.2 U2.A5 | length 103
  Top Layer w7.87: C24.2@571.35,616.98 571.74,616.58 U2.A5@571.74,593.36 ; C24.2@571.35,617.57 571.35,637.85 571.67,638.17 571.67,638.96 573.31,640.6 576.66,640.6 589.46,653.39 615.05,653.39 L2.2@620.95,659.3
DIGVDD: C10.1 U1.F1 | length 158.6
  Top Layer w7: U1.F1@602.84,188.99 626.13,188.99 628.44,191.31 v4(628.68,191.31)
  Mid Layer 1 w7: v4@628.68,190.94 628.8,190.94 629.11,190.63 629.11,190.51 631.69,187.93 649.72,169.9 649.72,146.84 696.14,100.41 v1(709.37,100.41)
GND: C1.1 C2.1 C3.1 C4.1 C5.2 C6.1 C7.1 C8.1 C9.2 C10.2 C11.1 C12.1 C13.1 C14.1 C15.1 C16.1 C17.1 C18.1 C20.1 C21.2 C22.1 C24.1 C25.1 C26.1 C28.2 C29.1 C30.1 F2.2 F2.5 F2.7 J1.2 pad.2 pad.3 TP14.1 TP19.1 TP24.1 TP25.1 TP26.1 TP30.1 U1.A1 U1.A7 U1.A13 U1.A18 U1.A20 U1.C5 U1.C7 U1.C9 U1.C11 U1.C13 U1.D1 U1.D5 U1.D7 U1.D9 U1.D11 U1.D13 U1.D16 U1.D20 U1.E3 U1.E5 U1.E7 U1.E9 U1.E11 U1.E13 U1.F7 U1.F9 U1.F11 U1.F13 U1.H20 U1.J1 U1.J7 U1.K1 U1.K20 U1.L3 U1.L9 U1.L18 U2.A6 U2.C2 U2.G4 U3.2 U5.B1 X1.2 X1.4 X2.2 X2.4 Z4.2 Z5.1 Z6.1 | length 1366.9
  Top Layer w4: U1.L18@491.21,230.34 U1.L18@491.27,230.41 ; v4@491.27,234.34 v4(491.33,234.4) ; U1.E3@587.69,175.21 587.96,175.21 601.47,161.7 U1.D1@601.47,161.43
  Top Layer w5: X2.4@439.85,664.22 X2.4@449.69,664.22 459.53,656.95 485.12,638.03 X2.2@494.97,630.76 ; 503.83,65.34 507.96,69.48 507.96,96.94 518.77,107.75 518.77,119.43 U1.A13@519.1,119.75 ; 559.14,99.4 559.14,117.06 559.57,117.49 559.57,119.53 U1.A7@560.12,120.08
  Top Layer w5.9: v4(464.43,220.2) U1.K20@477.42,216.56
  Top Layer w6: C9.2@559.14,69.29 559.14,99.4 ; U1.E5@573.9,175.21 U1.E3@586.45,175.21 ; U1.A1@601.47,120.08 601.47,119.57 603.34,117.7 603.34,116.14 ; 625.08,216.56 625.59,217.07
  Top Layer w6.5: U1.C9@546.34,147.64 U1.C7@560.12,147.64 ; U1.J1@601.47,202.78 601.74,202.51 608.08,202.51 609.6,201 v4@609.97,201
  Top Layer w6.8: v4@469.66,156.88 U1.D20@477.42,161.43 ; v4(469.66,189.48) U1.H20@477.42,192.26
  Top Layer w7: v4(475.89,110.55) 476.06,110.72 476.06,118.48 477.52,119.94 477.52,120.08 U1.A18@491.21,120.08 ; U1.L18@491.27,230.41 v4@491.27,234.34 ; U1.E7@559.71,174.8 U1.E7@560.12,175.21 ; v4(580.7,243.53) 587.58,236.65 587.58,230.69 U1.L3@587.69,230.58
  Top Layer w7.87: v2@487,580 488.8,578.2 498.11,578.2 506.58,569.73 v1(524.49,569.73) v1(536.31,569.73) ; U2.G4@559.93,522.11 559.93,510.3 563.86,506.36 C28.2@563.86,498.88 ; v13(564.78,498.66) 564.78,497.97 C28.2@565.24,497.51 ; U2.A6@583.55,593.36 583.55,600.16 586.27,602.89 v8(586.27,603.95) ; v8@585.52,603.2 v8(586.27,603.95) ; v2(596.35,634.69) 595.07,633.41 595.07,618.45 592.41,615.8 592.41,610.53 586.27,604.4 v8(586.27,603.95) ; U1.K1@601.47,216.56 625.08,216.56
  Top Layer w8: v3(548.15,174.8) U1.E7@559.71,174.8
  Top Layer w8.5: v3@370.29,58.16 U5.B1@384.27,44.18
  Top Layer w9: v3(369,61.33) 370.29,60.04 v3@370.29,58.16 ; v3@423.12,102.28 424.94,102.28 426.28,103.61 438.22,103.61 438.97,104.36 v4(451.57,104.36)
  Top Layer w9.4: U3.2@418.91,207.87 419,207.96 v4(419,218.5)
  Top Layer w10: v2(402.23,443.28) v2@404.85,443.28
  Top Layer w10.63: v8(619.97,592.76) 630.76,592.76 646.94,608.94 646.94,611.47 v8(651.46,615.99)
  Top Layer w12: X1.4@546.66,319.06 v3(564.45,334.41) ; v3@573.46,296.33 X1.2@591.93,285.59
  Top Layer w15: TP30.1@232.78,691.98 232.78,644.95 233.02,644.71 ; C6.1@417.43,403.76 417.43,435 ; v2(423.12,664.22) X2.4@439.85,664.22 ; C16.1@631.44,357.17 632.81,358.53 v2@632.81,379.6 ; v2@639.03,382.58 640.3,382.58 642.2,384.48 655.68,384.48 664.5,375.65 C5.2@664.5,373.68 ; 847,368 TP19.1@876.65,368
  Top Layer w20: C7.1@655.69,64.26 656.67,64.26 661.44,59.49 661.44,36.52 v3(665.78,32.18) ; C10.2@747.62,94.5 747.8,94.5 747.96,94.34 v2(747.96,67.87)
  Top Layer w25: v2(383.73,402.18) C6.1@413.03,402.18
  Mid Layer 1 w6.5: v4@609.97,201 609.97,200.62 616.06,194.54 616.06,185.92 618.48,183.49 637.33,164.65 637.89,164.65 637.89,129.66 646.02,121.53 646.02,110.55 v6(647.79,108.78)
  Mid Layer 1 w7.87: v1(524.49,569.73) v12@535.93,569.73
  Mid Layer 1 w10: v3@863.03,366.2 v3@863.03,367.76
  Mid Layer 1 w15: 832.24,367.76 v3@863.03,367.76
  Mid Layer 2 w6: v12@536.31,569.7 v12@536.31,569.89
  Mid Layer 2 w15: 826.42,368 TP19.1@876.65,368
  Mid-Layer 3 w8: 878,346 TP19.1@878,360.19
  Mid-Layer 3 w15: 232,639.44 232.78,640.23 TP30.1@232.78,691.98 ; 829.12,370.28 831.4,368
  Mid-Layer 3 w17: 831.4,368 TP19.1@876.65,368
  Mid-Layer 4 w15: TP30.1@232.78,691.98 232.78,640.21 235,638
  Bottom Layer w8: v3@863.03,366.9 v3@863.03,367.76 ; TP19.1@876.65,364.4 876.79,364.4 878,363.19 878,344.02
  Bottom Layer w12: 838.79,392 v3@863.03,367.76
  Bottom Layer w17: 232.78,644.21 TP30.1@232.78,679.18
  other v1: 478.7,61.33 707.55,142.55 761.37,142.84 725.54,143.33 744.68,143.19 735.88,153.02 752.52,152.13 699.77,153.55 718.18,153.15 764.06,159.3 688.89,161.99 710.02,161.61 726.97,161.61 744.83,161.26 773.86,169.37 678.44,172.26 688.72,182.24 769.2,182.43 673.24,184.76 687.86,194.07 769.31,196.2 673.51,205.56 689.5,206.51 768.77,211.74 661.09,214.33 679.81,215.23 642.42,217.07 653.02,221.77 670.14,221.46 688.72,221.64 768.11,227.01 767.88,242.04 768.77,254.86 769.31,266.89 747.96,271.84 792.27,272.91 806.2,276.12 769.78,279.64 738.84,282.26 782.43,282.18 754.3,283.09 795.73,286.91 814.27,286.8 769.31,293.74 783.15,298.6 738.84,299.83 754.3,299.45 796.93,301.34 813.14,301.54 768.08,309.05 748.04,311.52 782.65,313.98 794.37,315.51 813.14,316.27 775.14,324.5 757.78,327.38 804.66,328.82 790.87,329.61 816.46,336.33 769.68,338.82 803.46,340.82 785.28,341.57 536.31,569.73
  other v2: 191.07,26.99 307.21,26.18 857.28,39.08 308.15,61.33 192,62.15 386.59,78.48 823.73,85.18 298.73,89.18 366.45,99.11 327.22,108.78 294.73,120.95 220.23,150.2 384.68,156.87 220.23,184.76 293.04,193.07 327.22,201.38 220.23,218.5 295.09,220.5 393,246 287.8,247 339.18,253.18 220.23,267.65 287.8,293.74 219.53,299.45 338.18,308.64 367.31,321.36 219.53,330.84 287.8,330.84 335,337.48 373.18,366.32 287.8,368 749.71,369.2 333.34,371.45 780.79,371.45 565.83,382.58 602.32,382.58 639.16,383.45 335,403.76 287.8,408 335,433 217.2,439 284.56,443.28 335,464.88 253.9,466.14 371,471 433.49,474.28 285.21,476.6 217.2,479.18 335,498.66 386.39,498.88 253,500.73 443.73,500.36 284,516 218.41,519.75 336.11,532.94 373.18,533.92 415.24,534.91 463,534.91 253,542 286.96,555.65 219.53,557.92 415.24,579.98 491.2,579.58 252,581 311.8,580.5 356.74,581.16 291.91,597.33 219.53,598.08 449.69,599.87 380.79,600.24 341.05,602.83 675.09,615.99 254.6,621.52
  other v3: 459,22 793.73,22.18 549.99,53.01 350,72 341.05,91.24 423.12,101.28 398.7,102.28 569.26,153.02 544.63,153.13 530.12,166.39 566.47,170.85 573.44,295.3 506.22,307.39 404.83,313.66 863.03,368.9 497.54,369.37 729.16,383.87 532,384.95 844,473 565.83,481.36 753,559 415.24,604.18 837.16,619 647.9,639.44 838.89,646.74 717.33,651.5 233.03,664.43 593.55,674.38
  other v4: 518.77,147.64 468.65,156.88 504.99,161.43 609.97,201.76 546.22,230.34 439.16,280.3
  other v6: 662.18,95.18 725.96,215.52 741.82,224.17 711.22,225.09 726.87,234.77 697.47,236.49 742.82,241.53 713.61,245.47 697.76,253.49 729.62,253.35 713.61,261.94
  other v8: 528.04,616.98 593.79,616.98 528.04,638.63 528.04,660.28
  other v12: 524.51,569.7 536.31,570.4
NetA1_4: A1.4 Z1.2
NetC29_2: C29.2 L3.2 L4.1 | length 42.3
  Top Layer w11.81: L4.1@428.04,557.92 449.1,557.92 L3.2@470.36,557.92
NetC30_2: C30.2 L4.2 L5.1 | length 42.3
  Top Layer w11.81: L5.1@360.12,557.92 L4.2@402.45,557.92
NetF2_3: F2.3 U3.5 | length 67.7
  Top Layer w5.76: F2.3@363.03,176.56 410.14,176.56 ccw(c410.14,185.41) 416.4,179.15 ccw(c410.35,185.2) 418.91,185.2 U3.5@418.91,192.13
NetF2_6: F2.6 R2.2 Z2.2
NetJ1_1: J1.1 R2.1
NetL3_1: L3.1 U2.D1 | length 30.1
  Top Layer w7.87: L3.1@494.37,557.92 U2.D1@524.49,557.92
NetZ1_1: Z1.1 Z3.1 Z4.1 Z5.2
NetZ2_1: Z2.1 Z3.2 Z6.2 | length 29.9
  Top Layer w29: Z2.1@255.83,186.88 255.83,216.74
NRESET: TP3.1 U2.D2 | length 613.5
  Mid Layer 1 w3.94: v5(524.49,553.61) 526.48,554.27 v1(536.31,557.55)
  Mid Layer 2 w3.94: v5(524.49,553.61) 510.69,553.61 477.52,520.44 469.23,512.15 469.23,508.22 469.05,508.04 469.05,446.77 507.65,408.18 745.55,408.18 759.55,394.18 781.38,394.18 802.2,415 840,415 860.27,435.27 865.97,435.27 873.67,442.98 890.18,442.98
P0.00: TP10.1 U2.G1 | length 540.1
  Top Layer w3.94: U2.G1@524.49,522.11 514.65,512.27 514.65,464.88 531.53,448 754.96,448 833.86,526.9 833.86,548.43 843.32,557.9 843.32,585.32 860.99,602.99 867.04,602.99 875.13,611.09 890.18,611.09
P0.01: TP2.1 U2.F1 | length 561.2
  Top Layer w3.94: U2.F1@524.49,533.92 518.59,533.92 503.83,519.16 503.83,460.23 525.5,438.56 760.43,438.56 843.29,521.42 843.29,543.73 852.73,553.16 852.73,553.96 ; 852.76,553.99 852.76,569.53 860.69,577.46 876.65,577.46 890.18,577.46
P0.02: TP16.1 U2.E2 | length 766.4
  Mid Layer 1 w3.94: v5(516.62,541.8) 528.43,541.8 534.8,544.98 v1(536.31,545.73)
  Mid Layer 2 w3.94: v5(516.62,541.8) 515.49,540.67 510.26,540.67 480.23,510.64 480.23,509.8 478.67,508.24 478.67,450.51 511.56,417.62 760.08,417.62 767.52,410.18 v7(769.73,410.18)
  Mid-Layer 3 w3.94: v7(769.73,410.18) 769.73,425.73 838.89,494.9 838.89,597.35 854.95,613.4 854.95,658.25 865.19,668.49 865.83,668.49 874.4,677.06 874.4,678.33 887,678.33 TP16.1@889.45,678.33 890.45,678.33
P0.03: TP1.1 U2.E1 | length 572.3
  Top Layer w3.94: U2.E1@524.49,545.73 515.74,545.73 493,522.99 493,451.21 515.08,429.13 765.86,429.13 852.73,516 852.73,526.7 868.56,542.54 890.18,542.54
P0.04: pad.4 U2.D3 | length 504.8
  Mid Layer 2 w3.94: v1(548.12,557.55) 541.43,555.32 540.11,554 537.89,547.34 521.54,530.97 511.7,530.97 505.79,525.07 505.79,524.81 488.1,507.12 488.1,489.08 488.11,454.41 495.94,446.58 497.1,446.58 516.63,427.05 829.68,427.05 841,438.37 v3(841,439)
  other v9: 548.12,557.55
P1.00/XL1: U2.C5 X3.2 | length 188.3
  Mid Layer 2 w3.94: v1(571.74,569.36) 605.31,602.92 636.46,602.92 668.09,634.55 688.09,634.55 708.46,614.17 v5(724.64,614.17)
  other v1: 724.55,614.07
  other v9: 571.74,569.36
P1.01/XL2: U2.C6 X3.1 | length 208.1
  Mid Layer 1 w3.94: v1(583.55,569.36) v5(599.3,571.33) v5@598.17,570.2 ; v5(749.45,601.35) 750,600.8 776.45,600.8 v1(777,600.24)
  Mid Layer 2 w4: v5(599.3,571.33) 605.79,571.33 622.95,588.48 654.36,588.48 656.01,588.48 662.62,595.08 664.96,597.43 703.57,597.43 707.4,601.26 749.36,601.26 v5(749.45,601.35)
P1.02/NFC1: TP20.1 U2.C7 | length 274.5
  Top Layer w3.94: U2.C7@595.36,569.36 595.89,569.36 596.88,568.37 599.3,568.37 632.7,534.98 677.13,534.98 699.77,557.62 699.77,620.76 684.13,636.4 684.13,649.12 670.6,662.66 TP20.1@670.6,691.98
P1.03/NFC2: TP22.1 U2.D5 | length 660.6
  Mid Layer 2 w3.94: v9(571.74,557.55) 573.24,558.11 579.61,560.5 606.19,560.5
  Mid Layer 2 w4: TP22.1@381.41,686.83 383.18,685.06 383.18,662.73 400.44,645.47 449.02,645.47 461,657.45 627.57,657.45 681.09,657.45 707.46,631.08 730.13,631.08 737.36,623.85 748.34,623.85 754.59,617.6 754.59,617.28 764.2,607.67 764.2,591.77 758.03,585.6 666.56,585.6 659.18,578.21 623.91,578.21 606.19,560.5
  other v1: 571.74,557.55
P1.04/AIN0/GRANT: U1.A11 U2.D6 | length 992.3
  Top Layer w4.5: v3(461,44) 462.18,45.18 502.21,45.18 520.13,63.1 520.13,93.76 532.56,106.19 U1.A11@532.56,120.08
  Mid Layer 1 w3.94: v1(583.55,557.55) 591.42,557.55 v5(599.3,549.67)
  Mid Layer 2 w3.94: v5(599.3,549.67) 610.02,549.67 624.71,534.98 659.79,534.98 676.82,552.01 676.82,569.19 v3(676.93,569.29)
  Mid-Layer 4 w4: v3(461,44) 464.18,44 473.36,53.18 507.04,53.18 516.92,63.06 516.92,98.92 519.33,101.33 540.03,122.03 574.03,122.03 617.21,165.21 617.21,224.82 582.79,259.24 547,295.03 547,377.51 547.86,378.38 547.86,391.52 547,392.38 547,403.18 575.49,431.67 608.24,431.67 659.78,483.22 659.78,532.81 679.2,552.23 679.2,556.23 ; v3(676.93,569.29) 679.17,567.04 679.17,556.26
P1.05/AIN1/REQ: U1.A5 U2.E6 | length 1054.4
  Top Layer w5: v4(571.74,108.78) 571.74,109.7 573.9,111.86 U1.A5@573.9,120.08
  Mid Layer 1 w3.94: v1(583.55,545.73) 584.3,544.98 588.24,544.98 v5(599.3,533.92)
  Mid Layer 2 w3.94: v5(599.3,533.92) 610.61,533.92 619.03,525.51 647.79,525.51
  Mid Layer 2 w4: v4(571.74,108.78) 610.02,108.78 671.99,46.81 716.34,46.81 v3@727.34,35.82 ; 647.79,525.51 665.85,525.51 674.15,533.81 745.63,533.81 752,540.18 773.6,540.18 778.8,534.98 795.87,534.98 v7(796.93,533.92)
  Mid-Layer 4 w4: v3(725.97,35.84) 764.96,35.84 779.58,50.46 815.78,50.46 843.23,77.91 843.23,114.93 843.73,115.43 843.73,115.87 852.23,124.37 852.23,276.25 820.73,307.75 820.73,342.6 831.18,353.04 831.18,411.47 812.18,430.47 812.18,516.73 796.93,531.98 v7(796.93,533.92)
  other v5: 571.74,108.78
P1.06/AIN2_BUCKEN: U1.J5 U2.D7 | length 1163.9
  Top Layer w3.94: U2.D7@595.36,557.55 596.11,557.55 597.48,556.17 598.35,556.17 629.06,525.46 647.79,525.46 720.42,525.46 732.61,537.64 733.31,538.2 ccw(c725.54,552) 734.58,539 771.09,539 v3(788.32,556.23)
  Mid Layer 1 w4: v4(573.9,202.78) 574.95,202.78 578.24,199.49 578.53,199.49 594.06,183.96 603.52,183.96 626.09,161.4 626.09,99.08 702.17,23 v3(705,23)
  Mid-Layer 4 w4: v3(705,23) 707.25,20.75 712.47,20.75 713.22,20 719.37,20 ; 719.4,19.98 732.54,19.98 ; 732.57,20 739.9,20 746.24,26.34 770.49,26.34 784.81,40.66 820.29,40.66 852.73,73.1 852.73,110.99 861.73,119.99 861.73,281.14 830.23,312.64 830.23,338.66 840.68,349.11 840.68,415.41 823.73,432.36 823.73,531.18 799.31,555.6 788.95,555.6 v3(788.32,556.23)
